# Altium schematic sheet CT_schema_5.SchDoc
size 479 x 328 mm
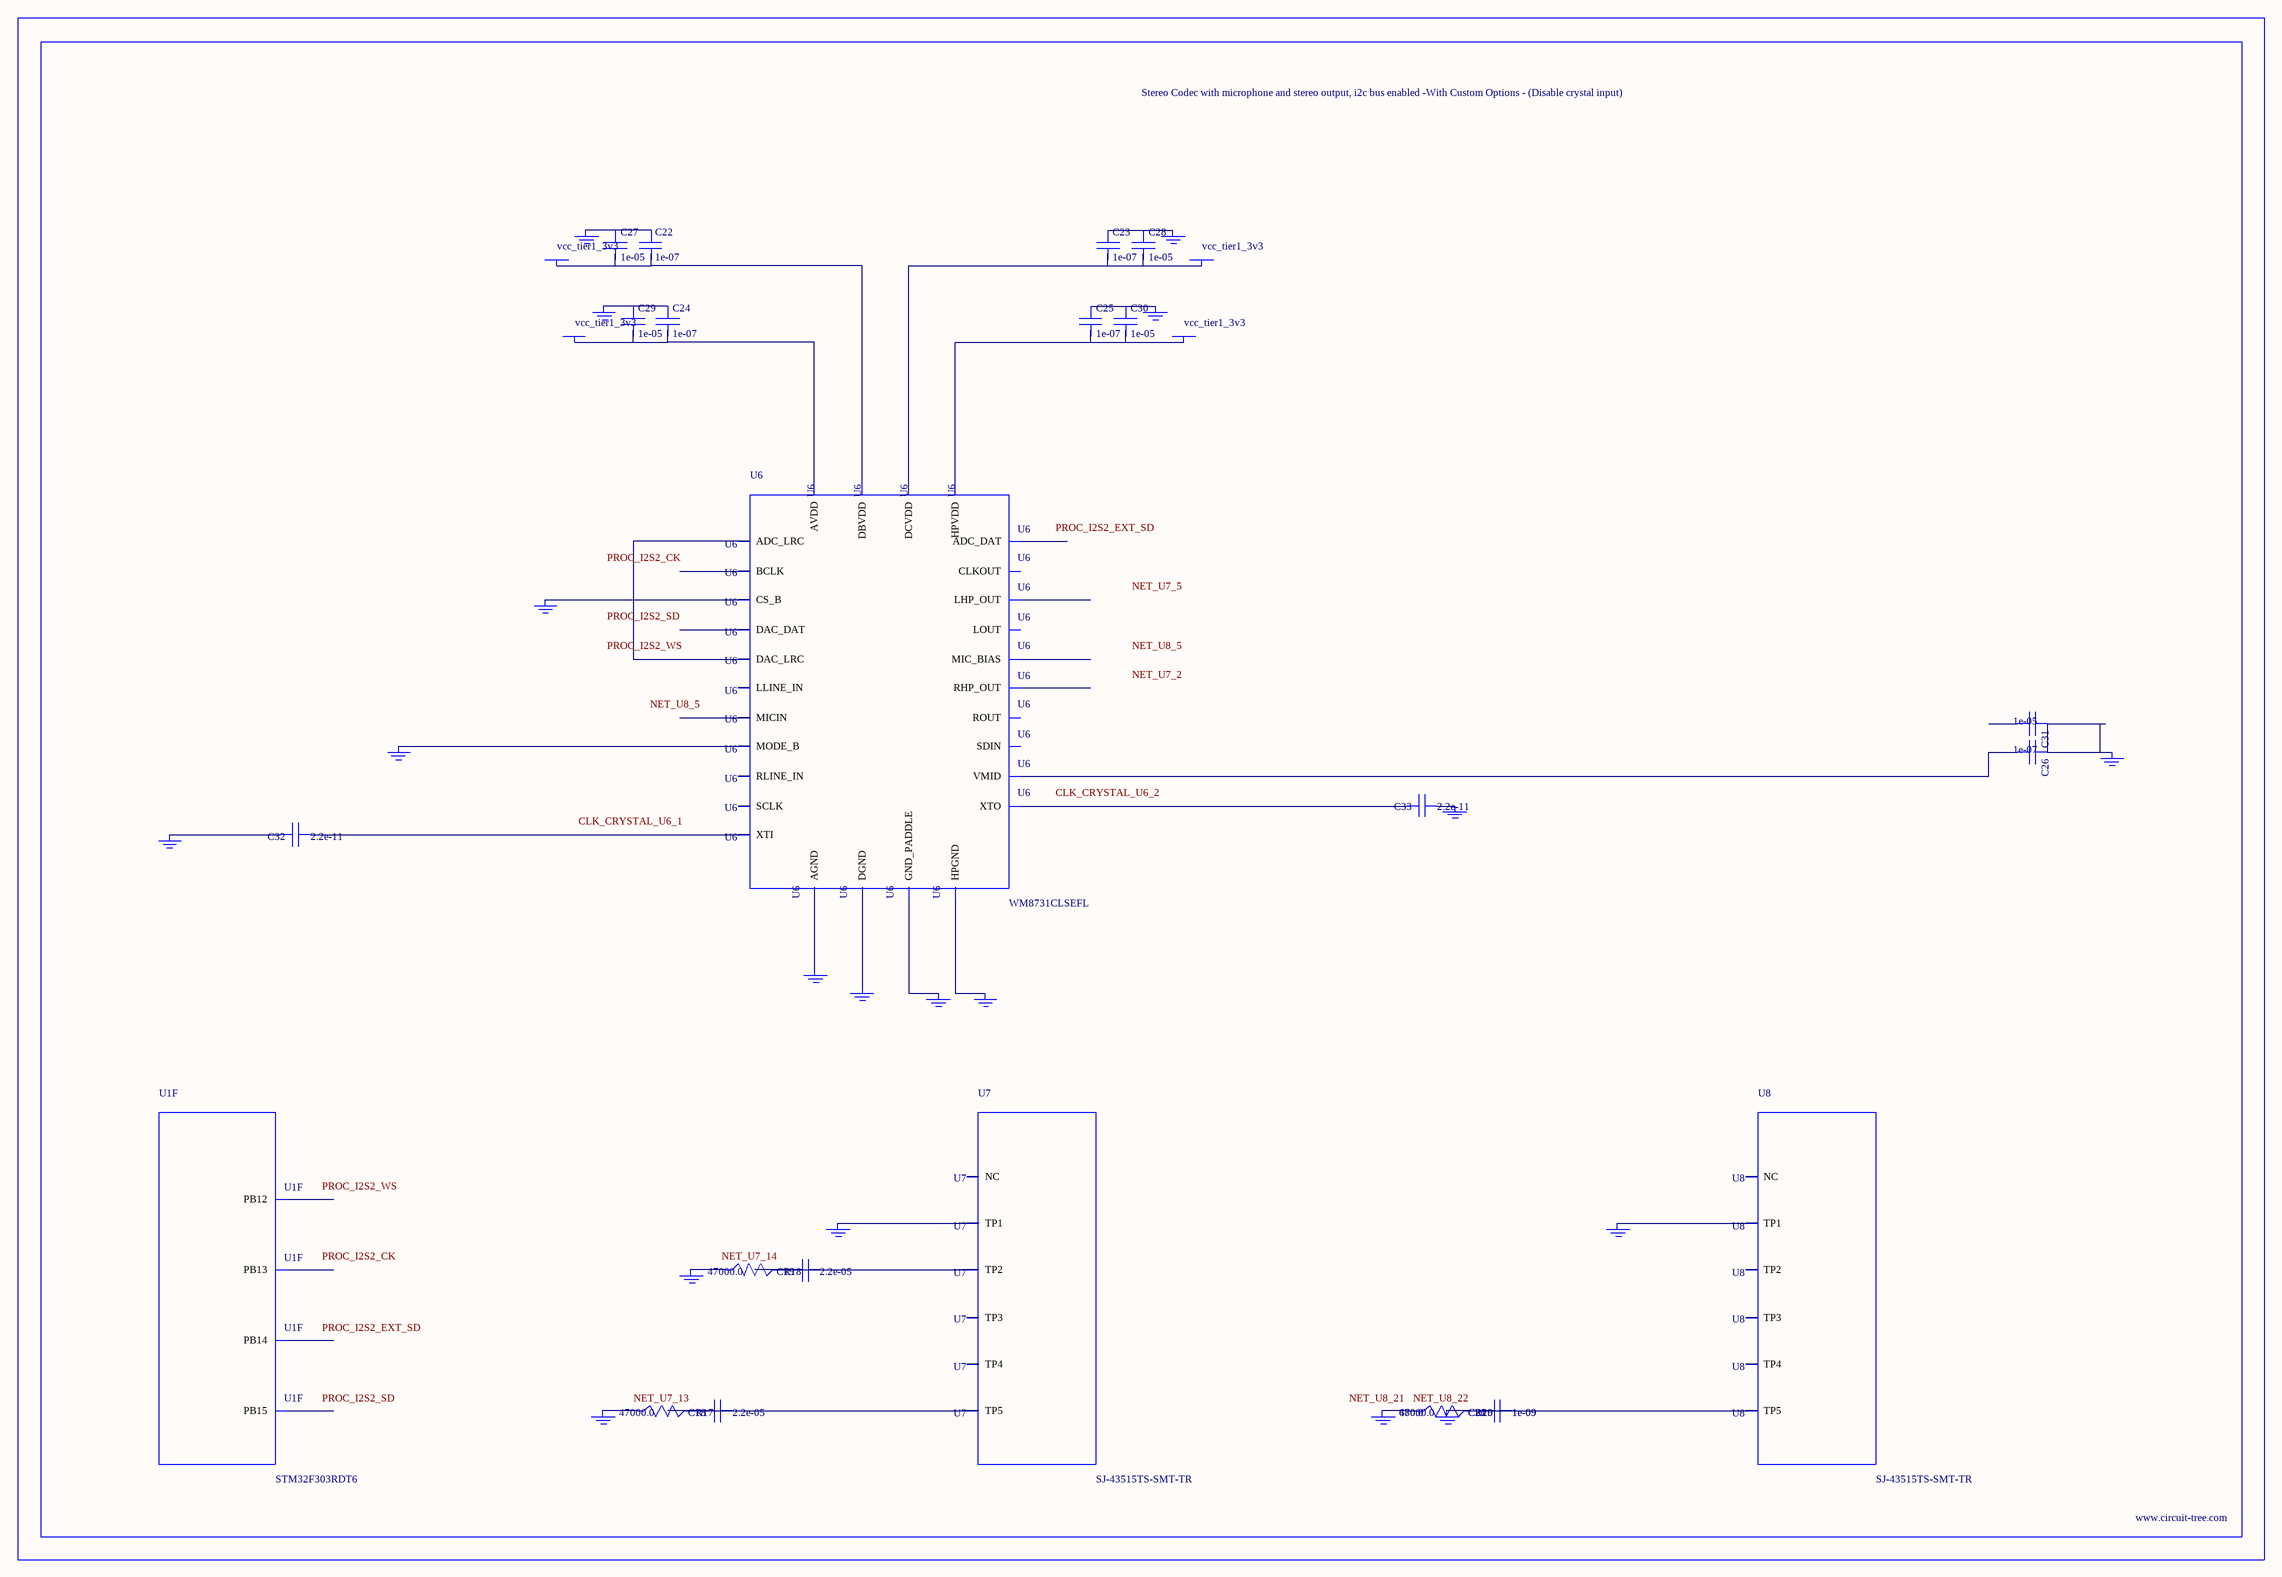
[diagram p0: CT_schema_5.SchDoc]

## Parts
BORDER4  (no value)
C18  2.2e-05  [C1210]
C19  2.2e-05  [C1210]
C20  1e-09  [C0402]
C21  1e-09  [C0402]
C22  1e-07  [C0402]
C23  1e-07  [C0402]
C24  1e-07  [C0402]
C25  1e-07  [C0402]
C26  1e-07  [C0402]
C27  1e-05  [C0805]
C28  1e-05  [C0805]
C29  1e-05  [C0805]
C30  1e-05  [C0805]
C31  1e-05  [C0805]
C32  2.2e-11  [C0402]
C33  2.2e-11  [C0402]
GND_INSTANCE_4_0  (no value)
GND_INSTANCE_4_1  (no value)
GND_INSTANCE_4_2  (no value)
GND_INSTANCE_4_3  (no value)
GND_INSTANCE_4_4  (no value)
GND_INSTANCE_4_5  (no value)
GND_INSTANCE_4_6  (no value)
GND_INSTANCE_4_7  (no value)
GND_INSTANCE_4_8  (no value)
GND_INSTANCE_4_9  (no value)
GND_INSTANCE_4_10  (no value)
GND_INSTANCE_4_11  (no value)
GND_INSTANCE_4_12  (no value)
GND_INSTANCE_4_13  (no value)
GND_INSTANCE_4_14  (no value)
GND_INSTANCE_4_15  (no value)
GND_INSTANCE_4_16  (no value)
GND_INSTANCE_4_17  (no value)
GND_INSTANCE_4_18  (no value)
POWER_INSTANCE_4_0  vcc_tier1_3v3
POWER_INSTANCE_4_1  vcc_tier1_3v3
POWER_INSTANCE_4_2  vcc_tier1_3v3
POWER_INSTANCE_4_3  vcc_tier1_3v3
R17  47000.0  [R0603]
R18  47000.0  [R0603]
R19  47000.0  [R0603]
R20  680.0  [R0603]
U1  STM32F303RDT6  [LQFP64]  (part F of 7)
U6  WM8731CLSEFL  [QFN-28]
U7  SJ-43515TS-SMT-TR  [SJ-43515TS-SMT-TR]
U8  SJ-43515TS-SMT-TR  [SJ-43515TS-SMT-TR]

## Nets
NetC18_1: C18.1 C18.2 R17.2 U7.5(TP5)
NetC19_1: C19.1 C19.2 R18.2 U7.2(TP2)
NetC20_1: C20.1 C20.2 C21.1 C21.2 GND_INSTANCE_4_18.0(GND) R19.2 R20.2 U8.5(TP5)
NetC22_1: C22.1 C27.1 GND_INSTANCE_4_3.0(GND)
NetC22_2: C22.2 C27.2 POWER_INSTANCE_4_1.0(PWR) U6.5(DBVDD)
NetC23_1: C23.1 C28.1 GND_INSTANCE_4_2.0(GND)
NetC23_2: C23.2 C28.2 POWER_INSTANCE_4_0.0(PWR) U6.3(DCVDD)
NetC24_1: C24.1 C29.1 GND_INSTANCE_4_6.0(GND)
NetC24_2: C24.2 C29.2 POWER_INSTANCE_4_3.0(PWR) U6.18(AVDD)
NetC25_1: C25.1 C30.1 GND_INSTANCE_4_4.0(GND)
NetC25_2: C25.2 C30.2 POWER_INSTANCE_4_2.0(PWR) U6.12(HPVDD)
NetC26_1: C26.1 C31.1 GND_INSTANCE_4_7.0(GND)
NetC26_2: C26.2 U6.20(VMID)
NetC32_1: C32.1 U6.1(XTI)
NetC32_2: C32.2 GND_INSTANCE_4_0.0(GND)
NetC33_1: C33.1 GND_INSTANCE_4_1.0(GND)
NetC33_2: C33.2 U6.2(XTO)
NetGND_INSTANCE_4_5_0: GND_INSTANCE_4_5.0(GND) U6.15(HPGND)
NetGND_INSTANCE_4_8_0: GND_INSTANCE_4_8.0(GND) U6.25(MODE_B)
NetGND_INSTANCE_4_9_0: GND_INSTANCE_4_9.0(GND) U6.26(CS_B)
NetGND_INSTANCE_4_10_0: GND_INSTANCE_4_10.0(GND) U6.29(GND_PADDLE)
NetGND_INSTANCE_4_11_0: GND_INSTANCE_4_11.0(GND) U6.4(DGND)
NetGND_INSTANCE_4_12_0: GND_INSTANCE_4_12.0(GND) U6.19(AGND)
NetGND_INSTANCE_4_13_0: GND_INSTANCE_4_13.0(GND) U7.1(TP1)
NetGND_INSTANCE_4_14_0: GND_INSTANCE_4_14.0(GND) R18.1
NetGND_INSTANCE_4_15_0: GND_INSTANCE_4_15.0(GND) R17.1
NetGND_INSTANCE_4_16_0: GND_INSTANCE_4_16.0(GND) U8.1(TP1)
NetGND_INSTANCE_4_17_0: GND_INSTANCE_4_17.0(GND) R19.1 R20.1
NetU6_9: U6.9(DAC_LRC) U6.11(ADC_LRC)

Not connected (* = marked no-connect by the designer): C31 2; U1 33(PB12) 34(PB13) 35(PB14) 36(PB15); U6 6(CLKOUT) 7(BCLK) 8(DAC_DAT) 10(ADC_DAT) 13(LHP_OUT) 14(RHP_OUT) 16(LOUT) 17(ROUT) 21(MIC_BIAS) 22(MICIN) 23(RLINE_IN) 24(LLINE_IN) 27(SDIN) 28(SCLK); U7 3(TP3) 4(TP4) 6(NC); U8 2(TP2) 3(TP3) 4(TP4) 6(NC)

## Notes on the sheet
- Labels drawn without touching a wire or pin: CLK_CRYSTAL_U6_1, CLK_CRYSTAL_U6_2, NET_U7_2, NET_U7_5, NET_U7_13, NET_U7_14, NET_U8_5, NET_U8_21, NET_U8_22, PROC_I2S2_CK, PROC_I2S2_EXT_SD, PROC_I2S2_SD, PROC_I2S2_WS

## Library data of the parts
BORDER4 = BORDER_PAGE4
C18 C19 = C1210C224K5RACTU
C20 C21 = C0402C102K3RAC
C22-C26 = C0402C104K3RACTU
C27-C31 = C0805C106K8RACTU
C32 C33 = C0402C220K3RAC
GND_INSTANCE_4_0-GND_INSTANCE_4_18 = GND
POWER_INSTANCE_4_0-POWER_INSTANCE_4_3 = PWR
R17-R19 = RC0603JR-0747KL
R20 = RC0603JR-07680RL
